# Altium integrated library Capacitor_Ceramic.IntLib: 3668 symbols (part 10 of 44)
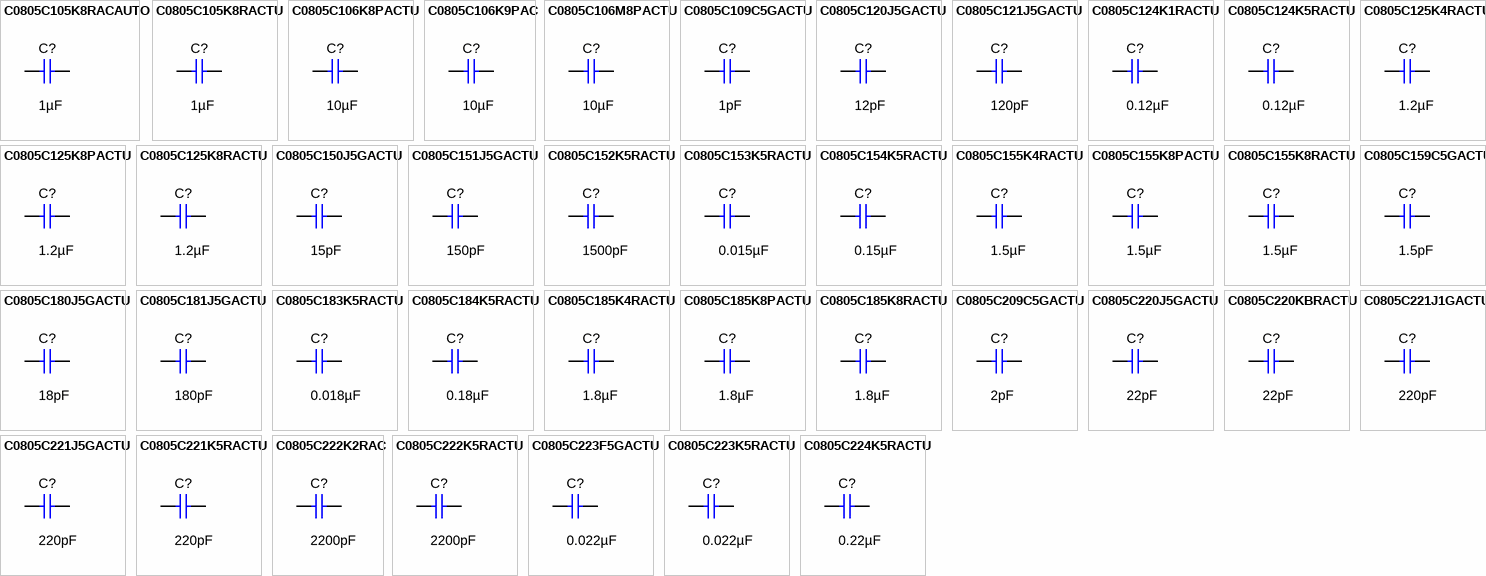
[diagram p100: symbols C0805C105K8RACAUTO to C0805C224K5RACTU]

## C0805C106K9PAC
designator C?  ValueDisplayed: 10µF  (hidden comment: C0805C106K9PAC)
CAP, CERM, 10 µF, 6.3 V,+/- 10%, X5R, 0805; Manufacturer: Kemet; Polarized: N; CompType: Capacitor; Value: 10uF; U/M: EA; Cap_F: 0.00001; Tolerance_%: 10; VDC_V: 6.3; Value2: 6.3V; TaMin_C: -55; TaMax_C: 85; Cap_Case: 0805; SizeArea_mm2: 2.5; SizeAreaWB_mm2: 6.75; SizeX_mm: 2; SizeY_mm: 1.25; SizeZ_mm: 1.45; AEC Category: Q200; Green_Lifecycle: Not Set; Green_REACh: Incomplete
signal-integrity model Cap
simulation model Cap
footprint 0805_HV
footprint 0805_HV1
footprint 0805
footprint 0805M
footprint 0805L
pins: 1, 2

## C0805C106M8PACTU
designator C?  ValueDisplayed: 10µF  (hidden comment: C0805C106M8PACTU)
CAP, CERM, 10 µF, 10 V,+/- 20%, X5R, 0805; Manufacturer: Kemet; Polarized: N; CompType: Capacitor; Value: 10uF; U/M: EA; Cap_F: 0.00001; Tolerance_%: 20; ESR_ohm: 0.003; Value1: 0.003 ohm; VDC_V: 10; Value2: 10V; IRMS_A: 11.43; TaMin_C: -55; TaMax_C: 85; Cap_Case: 0805; SizeArea_mm2: 2.5; SizeAreaWB_mm2: 6.75; SizeX_mm: 2; SizeY_mm: 1.25; SizeZ_mm: 1.45; AEC Category: Q200; Green_Lifecycle: Active; Green_REACh: Passed
signal-integrity model Cap
simulation model Cap
footprint 0805_HV
footprint 0805_HV1
footprint 0805
footprint 0805M
footprint 0805L
pins: 1, 2

## C0805C109C5GACTU
designator C?  ValueDisplayed: 1pF  (hidden comment: C0805C109C5GACTU)
CAP, CERM, 1 pF, 50 V,+/- 25%, C0G/NP0, 0805; Manufacturer: Kemet; Polarized: N; CompType: Capacitor; Value: 1pF; U/M: EA; Cap_F: 0.000000000001; Tolerance_%: 25; ESR_ohm: 0.84; Value1: 0.84 ohm; VDC_V: 50; Value2: 50V; IRMS_A: 0.023; TaMin_C: -55; TaMax_C: 125; Cap_Case: 0805; SizeArea_mm2: 2.5; SizeAreaWB_mm2: 6.75; SizeX_mm: 2; SizeY_mm: 1.25; SizeZ_mm: 1.45; AEC Category: Q200; Green_Lifecycle: Not Set; Green_REACh: Incomplete
signal-integrity model Cap
simulation model Cap
footprint 0805_HV
footprint 0805_HV1
footprint 0805
footprint 0805M
footprint 0805L
pins: 1, 2

## C0805C120J5GACTU
designator C?  ValueDisplayed: 12pF  (hidden comment: C0805C120J5GACTU)
CAP, CERM, 12 pF, 50 V,+/- 5%, C0G/NP0, 0805; Manufacturer: Kemet; Polarized: N; CompType: Capacitor; Value: 12pF; U/M: EA; Cap_F: 0.000000000012; Tolerance_%: 5; ESR_ohm: 0.252; Value1: 0.252 ohm; VDC_V: 50; Value2: 50V; IRMS_A: 0.265; TaMin_C: -55; TaMax_C: 125; Cap_Case: 0805; SizeArea_mm2: 2.5; SizeAreaWB_mm2: 6.75; SizeX_mm: 2; SizeY_mm: 1.25; SizeZ_mm: 1.45; AEC Category: Q200; Green_Lifecycle: Not Set; Green_REACh: Incomplete
signal-integrity model Cap
simulation model Cap
footprint 0805_HV
footprint 0805_HV1
footprint 0805
footprint 0805M
footprint 0805L
pins: 1, 2

## C0805C121J5GACTU
designator C?  ValueDisplayed: 120pF  (hidden comment: C0805C121J5GACTU)
CAP, CERM, 120 pF, 50 V,+/- 5%, C0G/NP0, 0805; Manufacturer: Kemet; Polarized: N; CompType: Capacitor; Value: 120pF; U/M: EA; Cap_F: 0.00000000012; Tolerance_%: 5; ESR_ohm: 0.066; Value1: 0.066 ohm; VDC_V: 50; Value2: 50V; IRMS_A: 0.615; TaMin_C: -55; TaMax_C: 125; Cap_Case: 0805; SizeArea_mm2: 2.5; SizeAreaWB_mm2: 6.75; SizeX_mm: 2; SizeY_mm: 1.25; SizeZ_mm: 1.45; AEC Category: Q200; Green_Lifecycle: Not Set; Green_REACh: Incomplete
signal-integrity model Cap
simulation model Cap
footprint 0805_HV
footprint 0805_HV1
footprint 0805
footprint 0805M
footprint 0805L
pins: 1, 2

## C0805C124K1RACTU
designator C?  ValueDisplayed: 0.12µF  (hidden comment: C0805C124K1RACTU)
CAP, CERM, 0.12 µF, 100 V,+/- 10%, X7R, 0805; Manufacturer: Kemet; Polarized: N; CompType: Capacitor; Value: 0.12uF; U/M: EA; Cap_F: 0.00000012; Tolerance_%: 10; ESR_ohm: 0.059; Value1: 0.059 ohm; VDC_V: 100; Value2: 100V; IRMS_A: 1.84; TaMin_C: -55; TaMax_C: 125; Cap_Case: 0805; SizeArea_mm2: 2.5; SizeAreaWB_mm2: 6.75; SizeX_mm: 2; SizeY_mm: 1.25; SizeZ_mm: 1.45; AEC Category: Q200; Green_Lifecycle: Not Set; Green_REACh: Incomplete
signal-integrity model Cap
simulation model Cap
footprint 0805_HV
footprint 0805_HV1
footprint 0805
footprint 0805M
footprint 0805L
pins: 1, 2

## C0805C124K5RACTU
designator C?  ValueDisplayed: 0.12µF  (hidden comment: C0805C124K5RACTU)
CAP, CERM, 0.12 µF, 50 V,+/- 10%, X7R, 0805; Manufacturer: Kemet; Polarized: N; CompType: Capacitor; Value: 0.12uF; U/M: EA; Cap_F: 0.00000012; Tolerance_%: 10; ESR_ohm: 0.059; Value1: 0.059 ohm; VDC_V: 50; Value2: 50V; IRMS_A: 1.84; TaMin_C: -55; TaMax_C: 125; Cap_Case: 0805; SizeArea_mm2: 2.5; SizeAreaWB_mm2: 6.75; SizeX_mm: 2; SizeY_mm: 1.25; SizeZ_mm: 1.45; AEC Category: Q200; Green_Lifecycle: Not Set; Green_REACh: Incomplete
signal-integrity model Cap
simulation model Cap
footprint 0805_HV
footprint 0805_HV1
footprint 0805
footprint 0805M
footprint 0805L
pins: 1, 2

## C0805C125K4RACTU
designator C?  ValueDisplayed: 1.2µF  (hidden comment: C0805C125K4RACTU)
CAP, CERM, 1.2 µF, 16 V,+/- 10%, X7R, 0805; Manufacturer: Kemet; Polarized: N; CompType: Capacitor; Value: 1.2uF; U/M: EA; Cap_F: 0.0000012; Tolerance_%: 10; ESR_ohm: 0.01; Value1: 0.01 ohm; VDC_V: 16; Value2: 16V; IRMS_A: 11.37; TaMin_C: -55; TaMax_C: 125; Cap_Case: 0805; SizeArea_mm2: 2.5; SizeAreaWB_mm2: 6.75; SizeX_mm: 2; SizeY_mm: 1.25; SizeZ_mm: 1.45; AEC Category: Q200; Green_Lifecycle: Not Set; Green_REACh: Incomplete
signal-integrity model Cap
simulation model Cap
footprint 0805_HV
footprint 0805_HV1
footprint 0805
footprint 0805M
footprint 0805L
pins: 1, 2

## C0805C125K8PACTU
designator C?  ValueDisplayed: 1.2µF  (hidden comment: C0805C125K8PACTU)
CAP, CERM, 1.2 µF, 10 V,+/- 10%, X5R, 0805; Manufacturer: Kemet; Polarized: N; CompType: Capacitor; Value: 1.2uF; U/M: EA; Cap_F: 0.0000012; Tolerance_%: 10; ESR_ohm: 0.009; Value1: 0.009 ohm; Value2: 10V; IRMS_A: 5.54; TaMin_C: -55; TaMax_C: 85; Cap_Case: 0805; SizeArea_mm2: 2.5; SizeAreaWB_mm2: 6.75; SizeX_mm: 2; SizeY_mm: 1.25; SizeZ_mm: 1.45; AEC Category: Q200; Green_Lifecycle: Not Set; Green_REACh: Incomplete
signal-integrity model Cap
simulation model Cap
footprint 0805_HV
footprint 0805_HV1
footprint 0805
footprint 0805M
footprint 0805L
pins: 1, 2

## C0805C125K8RACTU
designator C?  ValueDisplayed: 1.2µF  (hidden comment: C0805C125K8RACTU)
CAP, CERM, 1.2 µF, 10 V,+/- 10%, X7R, 0805; Manufacturer: Kemet; Polarized: N; CompType: Capacitor; Value: 1.2uF; U/M: EA; Cap_F: 0.0000012; Tolerance_%: 10; ESR_ohm: 0.01; Value1: 0.01 ohm; Value2: 10V; IRMS_A: 11.37; TaMin_C: -55; TaMax_C: 125; Cap_Case: 0805; SizeArea_mm2: 2.5; SizeAreaWB_mm2: 6.75; SizeX_mm: 2; SizeY_mm: 1.25; SizeZ_mm: 1.45; AEC Category: Q200; Green_Lifecycle: Not Set; Green_REACh: Incomplete
signal-integrity model Cap
simulation model Cap
footprint 0805_HV
footprint 0805_HV1
footprint 0805
footprint 0805M
footprint 0805L
pins: 1, 2

## C0805C150J5GACTU
designator C?  ValueDisplayed: 15pF  (hidden comment: C0805C150J5GACTU)
CAP, CERM, 15 pF, 50 V,+/- 5%, C0G/NP0, 0805; Manufacturer: Kemet; Polarized: N; CompType: Capacitor; Value: 15pF; U/M: EA; Cap_F: 0.000000000015; Tolerance_%: 5; ESR_ohm: 0.217; Value1: 0.217 ohm; VDC_V: 50; Value2: 50V; IRMS_A: 0.331; TaMin_C: -55; TaMax_C: 125; Cap_Case: 0805; SizeArea_mm2: 2.5; SizeAreaWB_mm2: 6.75; SizeX_mm: 2; SizeY_mm: 1.25; SizeZ_mm: 1.45; AEC Category: Q200; Green_Lifecycle: Not Set; Green_REACh: Incomplete
signal-integrity model Cap
simulation model Cap
footprint 0805_HV
footprint 0805_HV1
footprint 0805
footprint 0805M
footprint 0805L
pins: 1, 2

## C0805C151J5GACTU
designator C?  ValueDisplayed: 150pF  (hidden comment: C0805C151J5GACTU)
CAP, CERM, 150 pF, 50 V,+/- 5%, C0G/NP0, 0805; Manufacturer: Kemet; Polarized: N; CompType: Capacitor; Value: 150pF; U/M: EA; Cap_F: 0.00000000015; Tolerance_%: 5; ESR_ohm: 0.06; Value1: 0.06 ohm; VDC_V: 50; Value2: 50V; IRMS_A: 0.676; TaMin_C: -55; TaMax_C: 125; Cap_Case: 0805; SizeArea_mm2: 2.5; SizeAreaWB_mm2: 6.75; SizeX_mm: 2; SizeY_mm: 1.25; SizeZ_mm: 1.45; AEC Category: Q200; Green_Lifecycle: Active; Green_REACh: Passed
signal-integrity model Cap
simulation model Cap
footprint 0805_HV
footprint 0805_HV1
footprint 0805
footprint 0805M
footprint 0805L
pins: 1, 2

## C0805C152K5RACTU
designator C?  ValueDisplayed: 1500pF  (hidden comment: C0805C152K5RACTU)
CAP, CERM, 1500 pF, 50 V,+/- 10%, X7R, 0805; Manufacturer: Kemet; Polarized: N; CompType: Capacitor; Value: 1500pF; U/M: EA; Cap_F: 0.0000000015; Tolerance_%: 10; ESR_ohm: 0.475; Value1: 0.475 ohm; VDC_V: 50; Value2: 50V; IRMS_A: 0.188; TaMin_C: -55; TaMax_C: 125; Cap_Case: 0805; SizeArea_mm2: 2.5; SizeAreaWB_mm2: 6.75; SizeX_mm: 2; SizeY_mm: 1.25; SizeZ_mm: 1.45; AEC Category: Q200; Green_Lifecycle: Not Set; Green_REACh: Incomplete
signal-integrity model Cap
simulation model Cap
footprint 0805_HV
footprint 0805_HV1
footprint 0805
footprint 0805M
footprint 0805L
pins: 1, 2

## C0805C153K5RACTU
designator C?  ValueDisplayed: 0.015µF  (hidden comment: C0805C153K5RACTU)
CAP, CERM, 0.015 µF, 50 V,+/- 10%, X7R, 0805; Manufacturer: Kemet; Polarized: N; CompType: Capacitor; Value: 0.015uF; U/M: EA; Cap_F: 0.000000015; Tolerance_%: 10; ESR_ohm: 0.124; Value1: 0.124 ohm; VDC_V: 50; Value2: 50V; IRMS_A: 0.555; TaMin_C: -55; TaMax_C: 125; Cap_Case: 0805; SizeArea_mm2: 2.5; SizeAreaWB_mm2: 6.75; SizeX_mm: 2; SizeY_mm: 1.25; SizeZ_mm: 1.45; AEC Category: Q200; Green_Lifecycle: Not Set; Green_REACh: Incomplete
signal-integrity model Cap
simulation model Cap
footprint 0805_HV
footprint 0805_HV1
footprint 0805
footprint 0805M
footprint 0805L
pins: 1, 2

## C0805C154K5RACTU
designator C?  ValueDisplayed: 0.15µF  (hidden comment: C0805C154K5RACTU)
CAP, CERM, 0.15 µF, 50 V,+/- 10%, X7R, 0805; Manufacturer: Kemet; Polarized: N; CompType: Capacitor; Value: 0.15uF; U/M: EA; Cap_F: 0.00000015; Tolerance_%: 10; ESR_ohm: 0.054; Value1: 0.054 ohm; VDC_V: 50; Value2: 50V; IRMS_A: 2.09; TaMin_C: -55; TaMax_C: 125; Cap_Case: 0805; SizeArea_mm2: 2.5; SizeAreaWB_mm2: 6.75; SizeX_mm: 2; SizeY_mm: 1.25; SizeZ_mm: 1.45; AEC Category: Q200; Green_Lifecycle: Active; Green_REACh: Passed
signal-integrity model Cap
simulation model Cap
footprint 0805_HV
footprint 0805_HV1
footprint 0805
footprint 0805M
footprint 0805L
pins: 1, 2

## C0805C155K4RACTU
designator C?  ValueDisplayed: 1.5µF  (hidden comment: C0805C155K4RACTU)
CAP, CERM, 1.5 µF, 16 V,+/- 10%, X7R, 0805; Manufacturer: Kemet; Polarized: N; CompType: Capacitor; Value: 1.5uF; U/M: EA; Cap_F: 0.0000015; Tolerance_%: 10; ESR_ohm: 0.009; Value1: 0.009 ohm; VDC_V: 16; Value2: 16V; IRMS_A: 12.74; TaMin_C: -55; TaMax_C: 125; Cap_Case: 0805; SizeArea_mm2: 2.5; SizeAreaWB_mm2: 6.75; SizeX_mm: 2; SizeY_mm: 1.25; SizeZ_mm: 1.45; AEC Category: Q200; Green_Lifecycle: Not Set; Green_REACh: Incomplete
signal-integrity model Cap
simulation model Cap
footprint 0805_HV
footprint 0805_HV1
footprint 0805
footprint 0805M
footprint 0805L
pins: 1, 2

## C0805C155K8PACTU
designator C?  ValueDisplayed: 1.5µF  (hidden comment: C0805C155K8PACTU)
CAP, CERM, 1.5 µF, 10 V,+/- 10%, X5R, 0805; Manufacturer: Kemet; Polarized: N; CompType: Capacitor; Value: 1.5uF; U/M: EA; Cap_F: 0.0000015; Tolerance_%: 10; ESR_ohm: 0.009; Value1: 0.009 ohm; Value2: 10V; IRMS_A: 5.6; TaMin_C: -55; TaMax_C: 85; Cap_Case: 0805; SizeArea_mm2: 2.5; SizeAreaWB_mm2: 6.75; SizeX_mm: 2; SizeY_mm: 1.25; SizeZ_mm: 1.45; AEC Category: Q200; Green_Lifecycle: Not Set; Green_REACh: Incomplete
signal-integrity model Cap
simulation model Cap
footprint 0805_HV
footprint 0805_HV1
footprint 0805
footprint 0805M
footprint 0805L
pins: 1, 2

## C0805C155K8RACTU
designator C?  ValueDisplayed: 1.5µF  (hidden comment: C0805C155K8RACTU)
CAP, CERM, 1.5 µF, 10 V,+/- 10%, X7R, 0805; Manufacturer: Kemet; Polarized: N; CompType: Capacitor; Value: 1.5uF; U/M: EA; Cap_F: 0.0000015; Tolerance_%: 10; ESR_ohm: 0.009; Value1: 0.009 ohm; Value2: 10V; IRMS_A: 12.74; TaMin_C: -55; TaMax_C: 125; Cap_Case: 0805; SizeArea_mm2: 2.5; SizeAreaWB_mm2: 6.75; SizeX_mm: 2; SizeY_mm: 1.25; SizeZ_mm: 1.45; AEC Category: Q200; Green_Lifecycle: Not Set; Green_REACh: Incomplete
signal-integrity model Cap
simulation model Cap
footprint 0805_HV
footprint 0805_HV1
footprint 0805
footprint 0805M
footprint 0805L
pins: 1, 2

## C0805C159C5GACTU
designator C?  ValueDisplayed: 1.5pF  (hidden comment: C0805C159C5GACTU)
CAP, CERM, 1.5 pF, 50 V,+/- 17%, C0G/NP0, 0805; Manufacturer: Kemet; Polarized: N; CompType: Capacitor; Value: 1.5pF; U/M: EA; Cap_F: 0.0000000000015; Tolerance_%: 17; ESR_ohm: 0.765; Value1: 0.765 ohm; VDC_V: 50; Value2: 50V; IRMS_A: 0.032; TaMin_C: -55; TaMax_C: 125; Cap_Case: 0805; SizeArea_mm2: 2.5; SizeAreaWB_mm2: 6.75; SizeX_mm: 2; SizeY_mm: 1.25; SizeZ_mm: 1.45; AEC Category: Q200; Green_Lifecycle: Not Set; Green_REACh: Incomplete
signal-integrity model Cap
simulation model Cap
footprint 0805_HV
footprint 0805_HV1
footprint 0805
footprint 0805M
footprint 0805L
pins: 1, 2

## C0805C180J5GACTU
designator C?  ValueDisplayed: 18pF  (hidden comment: C0805C180J5GACTU)
CAP, CERM, 18 pF, 50 V,+/- 5%, C0G/NP0, 0805; Manufacturer: Kemet; Polarized: N; CompType: Capacitor; Value: 18pF; U/M: EA; Cap_F: 0.000000000018; Tolerance_%: 5; ESR_ohm: 0.193; Value1: 0.193 ohm; VDC_V: 50; Value2: 50V; IRMS_A: 0.38; TaMin_C: -55; TaMax_C: 125; Cap_Case: 0805; SizeArea_mm2: 2.5; SizeAreaWB_mm2: 6.75; SizeX_mm: 2; SizeY_mm: 1.25; SizeZ_mm: 1.45; AEC Category: Q200; Green_Lifecycle: Not Set; Green_REACh: Incomplete
signal-integrity model Cap
simulation model Cap
footprint 0805_HV
footprint 0805_HV1
footprint 0805
footprint 0805M
footprint 0805L
pins: 1, 2

## C0805C181J5GACTU
designator C?  ValueDisplayed: 180pF  (hidden comment: C0805C181J5GACTU)
CAP, CERM, 180 pF, 50 V,+/- 5%, C0G/NP0, 0805; Manufacturer: Kemet; Polarized: N; CompType: Capacitor; Value: 180pF; U/M: EA; Cap_F: 0.00000000018; Tolerance_%: 5; ESR_ohm: 0.053; Value1: 0.053 ohm; VDC_V: 50; Value2: 50V; IRMS_A: 0.782; TaMin_C: -55; TaMax_C: 125; Cap_Case: 0805; SizeArea_mm2: 2.5; SizeAreaWB_mm2: 6.75; SizeX_mm: 2; SizeY_mm: 1.25; SizeZ_mm: 1.45; AEC Category: Q200; Green_Lifecycle: Not Set; Green_REACh: Incomplete
signal-integrity model Cap
simulation model Cap
footprint 0805_HV
footprint 0805_HV1
footprint 0805
footprint 0805M
footprint 0805L
pins: 1, 2

## C0805C183K5RACTU
designator C?  ValueDisplayed: 0.018µF  (hidden comment: C0805C183K5RACTU)
CAP, CERM, 0.018 µF, 50 V,+/- 10%, X7R, 0805; Manufacturer: Kemet; Polarized: N; CompType: Capacitor; Value: 0.018uF; U/M: EA; Cap_F: 0.000000018; Tolerance_%: 10; ESR_ohm: 0.128; Value1: 0.128 ohm; VDC_V: 50; Value2: 50V; IRMS_A: 0.588; TaMin_C: -55; TaMax_C: 125; Cap_Case: 0805; SizeArea_mm2: 2.5; SizeAreaWB_mm2: 6.75; SizeX_mm: 2; SizeY_mm: 1.25; SizeZ_mm: 1.45; AEC Category: Q200; Green_Lifecycle: Not Set; Green_REACh: Incomplete
signal-integrity model Cap
simulation model Cap
footprint 0805_HV
footprint 0805_HV1
footprint 0805
footprint 0805M
footprint 0805L
pins: 1, 2

## C0805C184K5RACTU
designator C?  ValueDisplayed: 0.18µF  (hidden comment: C0805C184K5RACTU)
CAP, CERM, 0.18 µF, 50 V,+/- 10%, X7R, 0805; Manufacturer: Kemet; Polarized: N; CompType: Capacitor; Value: 0.18uF; U/M: EA; Cap_F: 0.00000018; Tolerance_%: 10; ESR_ohm: 0.051; Value1: 0.051 ohm; VDC_V: 50; Value2: 50V; IRMS_A: 2.33; TaMin_C: -55; TaMax_C: 125; Cap_Case: 0805; SizeArea_mm2: 2.5; SizeAreaWB_mm2: 6.75; SizeX_mm: 2; SizeY_mm: 1.25; SizeZ_mm: 1.45; AEC Category: Q200; Green_Lifecycle: Not Set; Green_REACh: Incomplete
signal-integrity model Cap
simulation model Cap
footprint 0805_HV
footprint 0805_HV1
footprint 0805
footprint 0805M
footprint 0805L
pins: 1, 2

## C0805C185K4RACTU
designator C?  ValueDisplayed: 1.8µF  (hidden comment: C0805C185K4RACTU)
CAP, CERM, 1.8 µF, 16 V,+/- 10%, X7R, 0805; Manufacturer: Kemet; Polarized: N; CompType: Capacitor; Value: 1.8uF; U/M: EA; Cap_F: 0.0000018; Tolerance_%: 10; ESR_ohm: 0.009; Value1: 0.009 ohm; VDC_V: 16; Value2: 16V; IRMS_A: 14.02; TaMin_C: -55; TaMax_C: 125; Cap_Case: 0805; SizeArea_mm2: 2.5; SizeAreaWB_mm2: 6.75; SizeX_mm: 2; SizeY_mm: 1.25; SizeZ_mm: 1.45; AEC Category: Q200; Green_Lifecycle: Not Set; Green_REACh: Incomplete
signal-integrity model Cap
simulation model Cap
footprint 0805_HV
footprint 0805_HV1
footprint 0805
footprint 0805M
footprint 0805L
pins: 1, 2

## C0805C185K8PACTU
designator C?  ValueDisplayed: 1.8µF  (hidden comment: C0805C185K8PACTU)
CAP, CERM, 1.8 µF, 10 V,+/- 10%, X5R, 0805; Manufacturer: Kemet; Polarized: N; CompType: Capacitor; Value: 1.8uF; U/M: EA; Cap_F: 0.0000018; Tolerance_%: 10; ESR_ohm: 0.005; Value1: 0.005 ohm; Value2: 10V; IRMS_A: 7.73; TaMin_C: -55; TaMax_C: 85; Cap_Case: 0805; SizeArea_mm2: 2.5; SizeAreaWB_mm2: 6.75; SizeX_mm: 2; SizeY_mm: 1.25; SizeZ_mm: 1.45; AEC Category: Q200; Green_Lifecycle: Not Set; Green_REACh: Incomplete
signal-integrity model Cap
simulation model Cap
footprint 0805_HV
footprint 0805_HV1
footprint 0805
footprint 0805M
footprint 0805L
pins: 1, 2

## C0805C185K8RACTU
designator C?  ValueDisplayed: 1.8µF  (hidden comment: C0805C185K8RACTU)
CAP, CERM, 1.8 µF, 10 V,+/- 10%, X7R, 0805; Manufacturer: Kemet; Polarized: N; CompType: Capacitor; Value: 1.8uF; U/M: EA; Cap_F: 0.0000018; Tolerance_%: 10; ESR_ohm: 0.009; Value1: 0.009 ohm; Value2: 10V; IRMS_A: 14.02; TaMin_C: -55; TaMax_C: 125; Cap_Case: 0805; SizeArea_mm2: 2.5; SizeAreaWB_mm2: 6.75; SizeX_mm: 2; SizeY_mm: 1.25; SizeZ_mm: 1.45; AEC Category: Q200; Green_Lifecycle: Not Set; Green_REACh: Incomplete
signal-integrity model Cap
simulation model Cap
footprint 0805_HV
footprint 0805_HV1
footprint 0805
footprint 0805M
footprint 0805L
pins: 1, 2

## C0805C209C5GACTU
designator C?  ValueDisplayed: 2pF  (hidden comment: C0805C209C5GACTU)
CAP, CERM, 2 pF, 50 V,+/- 13%, C0G/NP0, 0805; Manufacturer: Kemet; Polarized: N; CompType: Capacitor; Value: 2pF; U/M: EA; Cap_F: 0.000000000002; Tolerance_%: 13; ESR_ohm: 0.67; Value1: 0.67 ohm; VDC_V: 50; Value2: 50V; IRMS_A: 0.043; TaMin_C: -55; TaMax_C: 125; Cap_Case: 0805; SizeArea_mm2: 2.5; SizeAreaWB_mm2: 6.75; SizeX_mm: 2; SizeY_mm: 1.25; SizeZ_mm: 1.45; AEC Category: Q200; Green_Lifecycle: Not Set; Green_REACh: Incomplete
signal-integrity model Cap
simulation model Cap
footprint 0805_HV
footprint 0805_HV1
footprint 0805
footprint 0805M
footprint 0805L
pins: 1, 2

## C0805C220J5GACTU
designator C?  ValueDisplayed: 22pF  (hidden comment: C0805C220J5GACTU)
CAP, CERM, 22 pF, 50 V,+/- 5%, C0G/NP0, 0805; Manufacturer: Kemet; Polarized: N; CompType: Capacitor; Value: 22pF; U/M: EA; Cap_F: 0.000000000022; Tolerance_%: 5; ESR_ohm: 0.179; Value1: 0.179 ohm; VDC_V: 50; Value2: 50V; IRMS_A: 0.464; TaMin_C: -55; TaMax_C: 125; Cap_Case: 0805; SizeArea_mm2: 2.5; SizeAreaWB_mm2: 6.75; SizeX_mm: 2; SizeY_mm: 1.25; SizeZ_mm: 1.45; AEC Category: Q200; Green_Lifecycle: Not Set; Green_REACh: Incomplete
signal-integrity model Cap
simulation model Cap
footprint 0805_HV
footprint 0805_HV1
footprint 0805
footprint 0805M
footprint 0805L
pins: 1, 2

## C0805C220KBRACTU
designator C?  ValueDisplayed: 22pF  (hidden comment: C0805C220KBRACTU)
CAP, CERM, 22 pF, 630 V,+/- 10%, X7R, 0805; Manufacturer: Kemet; Polarized: N; CompType: Capacitor; Value: 22pF; U/M: EA; Cap_F: 0.000000000022; Tolerance_%: 10; VDC_V: 630; Value2: 630V; TaMin_C: -55; TaMax_C: 125; Cap_Case: 0805; SizeArea_mm2: 2.5; SizeAreaWB_mm2: 6.75; SizeX_mm: 2; SizeY_mm: 1.25; SizeZ_mm: 1.45; AEC Category: Q200; Green_Lifecycle: Active; Green_REACh: Passed
signal-integrity model Cap
simulation model Cap
footprint 0805_HV
footprint 0805_HV1
footprint 0805
footprint 0805M
footprint 0805L
pins: 1, 2

## C0805C221J1GACTU
designator C?  ValueDisplayed: 220pF  (hidden comment: C0805C221J1GACTU)
CAP, CERM, 220 pF, 100 V,+/- 5%, C0G/NP0, 0805; Manufacturer: Kemet; Polarized: N; CompType: Capacitor; Value: 220pF; U/M: EA; Cap_F: 0.00000000022; Tolerance_%: 5; ESR_ohm: 0.046; Value1: 0.046 ohm; VDC_V: 100; Value2: 100V; IRMS_A: 0.888; TaMin_C: -55; TaMax_C: 125; Cap_Case: 0805; SizeArea_mm2: 2.5; SizeAreaWB_mm2: 6.75; SizeX_mm: 2; SizeY_mm: 1.25; SizeZ_mm: 1.45; AEC Category: Q200; Green_Lifecycle: Not Set; Green_REACh: Incomplete
signal-integrity model Cap
simulation model Cap
footprint 0805_HV
footprint 0805_HV1
footprint 0805
footprint 0805M
footprint 0805L
pins: 1, 2

## C0805C221J5GACTU
designator C?  ValueDisplayed: 220pF  (hidden comment: C0805C221J5GACTU)
CAP, CERM, 220 pF, 50 V,+/- 5%, C0G/NP0, 0805; Manufacturer: Kemet; Polarized: N; CompType: Capacitor; Value: 220pF; U/M: EA; Cap_F: 0.00000000022; Tolerance_%: 5; ESR_ohm: 0.046; Value1: 0.046 ohm; VDC_V: 50; Value2: 50V; IRMS_A: 0.888; TaMin_C: -55; TaMax_C: 125; Cap_Case: 0805; SizeArea_mm2: 2.5; SizeAreaWB_mm2: 6.75; SizeX_mm: 2; SizeY_mm: 1.25; SizeZ_mm: 1.45; AEC Category: Q200; Green_Lifecycle: Not Set; Green_REACh: Incomplete
signal-integrity model Cap
simulation model Cap
footprint 0805_HV
footprint 0805_HV1
footprint 0805
footprint 0805M
footprint 0805L
pins: 1, 2

## C0805C221K5RACTU
designator C?  ValueDisplayed: 220pF  (hidden comment: C0805C221K5RACTU)
CAP, CERM, 220 pF, 50 V,+/- 10%, X7R, 0805; Manufacturer: Kemet; Polarized: N; CompType: Capacitor; Value: 220pF; U/M: EA; Cap_F: 0.00000000022; Tolerance_%: 10; ESR_ohm: 1.414; Value1: 1.414 ohm; VDC_V: 50; Value2: 50V; IRMS_A: 0.111; TaMin_C: -55; TaMax_C: 125; Cap_Case: 0805; SizeArea_mm2: 2.5; SizeAreaWB_mm2: 6.75; SizeX_mm: 2; SizeY_mm: 1.25; SizeZ_mm: 1.45; AEC Category: Q200; Green_Lifecycle: Active; Green_REACh: Passed
signal-integrity model Cap
simulation model Cap
footprint 0805_HV
footprint 0805_HV1
footprint 0805
footprint 0805M
footprint 0805L
pins: 1, 2

## C0805C222K2RAC
designator C?  ValueDisplayed: 2200pF  (hidden comment: C0805C222K2RAC)
CAP, CERM, 2200 pF, 200 V,+/- 10%, X7R, 0805; Manufacturer: Kemet; Polarized: N; CompType: Capacitor; Value: 2200pF; U/M: EA; Cap_F: 0.0000000022; Tolerance_%: 10; VDC_V: 200; Value2: 200V; TaMin_C: -55; TaMax_C: 125; Cap_Case: 0805; SizeArea_mm2: 2.5; SizeAreaWB_mm2: 6.75; SizeX_mm: 2; SizeY_mm: 1.25; SizeZ_mm: 1.45; AEC Category: Q200
signal-integrity model Cap
simulation model Cap
footprint 0805_HV
footprint 0805_HV1
footprint 0805
footprint 0805M
footprint 0805L
pins: 1, 2

## C0805C222K5RACTU
designator C?  ValueDisplayed: 2200pF  (hidden comment: C0805C222K5RACTU)
CAP, CERM, 2200 pF, 50 V,+/- 10%, X7R, 0805; Manufacturer: Kemet; Polarized: N; CompType: Capacitor; Value: 2200pF; U/M: EA; Cap_F: 0.0000000022; Tolerance_%: 10; ESR_ohm: 0.4; Value1: 0.4 ohm; VDC_V: 50; Value2: 50V; IRMS_A: 0.251; TaMin_C: -55; TaMax_C: 125; Cap_Case: 0805; SizeArea_mm2: 2.5; SizeAreaWB_mm2: 6.75; SizeX_mm: 2; SizeY_mm: 1.25; SizeZ_mm: 1.45; AEC Category: Q200; Green_Lifecycle: Active; Green_REACh: Passed
signal-integrity model Cap
simulation model Cap
footprint 0805_HV
footprint 0805_HV1
footprint 0805
footprint 0805M
footprint 0805L
pins: 1, 2

## C0805C223F5GACTU
designator C?  ValueDisplayed: 0.022µF  (hidden comment: C0805C223F5GACTU)
CAP, CERM, 0.022 µF, 50 V,+/- 1%, C0G/NP0, 0805; Manufacturer: Kemet; Polarized: N; CompType: Capacitor; Value: 0.022uF; U/M: EA; Cap_F: 0.000000022; Tolerance_%: 1; VDC_V: 50; Value2: 50V; TaMin_C: -55; TaMax_C: 125; Cap_Case: 0805; SizeArea_mm2: 2.5; SizeAreaWB_mm2: 6.75; SizeX_mm: 2; SizeY_mm: 1.25; SizeZ_mm: 1.45; AEC Category: Q200; Green_Lifecycle: Not Set; Green_REACh: Incomplete
signal-integrity model Cap
simulation model Cap
footprint 0805_HV
footprint 0805_HV1
footprint 0805
footprint 0805M
footprint 0805L
pins: 1, 2

## C0805C223K5RACTU
designator C?  ValueDisplayed: 0.022µF  (hidden comment: C0805C223K5RACTU)
CAP, CERM, 0.022 µF, 50 V,+/- 10%, X7R, 0805; Manufacturer: Kemet; Polarized: N; CompType: Capacitor; Value: 0.022uF; U/M: EA; Cap_F: 0.000000022; Tolerance_%: 10; ESR_ohm: 0.125; Value1: 0.125 ohm; VDC_V: 50; Value2: 50V; IRMS_A: 0.645; TaMin_C: -55; TaMax_C: 125; Cap_Case: 0805; SizeArea_mm2: 2.5; SizeAreaWB_mm2: 6.75; SizeX_mm: 2; SizeY_mm: 1.25; SizeZ_mm: 1.45; AEC Category: Q200; Green_Lifecycle: Active; Green_REACh: Passed
signal-integrity model Cap
simulation model Cap
footprint 0805_HV
footprint 0805_HV1
footprint 0805
footprint 0805M
footprint 0805L
pins: 1, 2

## C0805C224K5RACTU
designator C?  ValueDisplayed: 0.22µF  (hidden comment: C0805C224K5RACTU)
CAP, CERM, 0.22 µF, 50 V,+/- 10%, X7R, 0805; Manufacturer: Kemet; Polarized: N; CompType: Capacitor; Value: 0.22uF; U/M: EA; Cap_F: 0.00000022; Tolerance_%: 10; ESR_ohm: 0.046; Value1: 0.046 ohm; VDC_V: 50; Value2: 50V; IRMS_A: 2.65; TaMin_C: -55; TaMax_C: 125; Cap_Case: 0805; SizeArea_mm2: 2.5; SizeAreaWB_mm2: 6.75; SizeX_mm: 2; SizeY_mm: 1.25; SizeZ_mm: 1.45; AEC Category: Q200; Green_Lifecycle: Active; Green_REACh: Passed
signal-integrity model Cap
simulation model Cap
footprint 0805_HV
footprint 0805_HV1
footprint 0805
footprint 0805M
footprint 0805L
pins: 1, 2

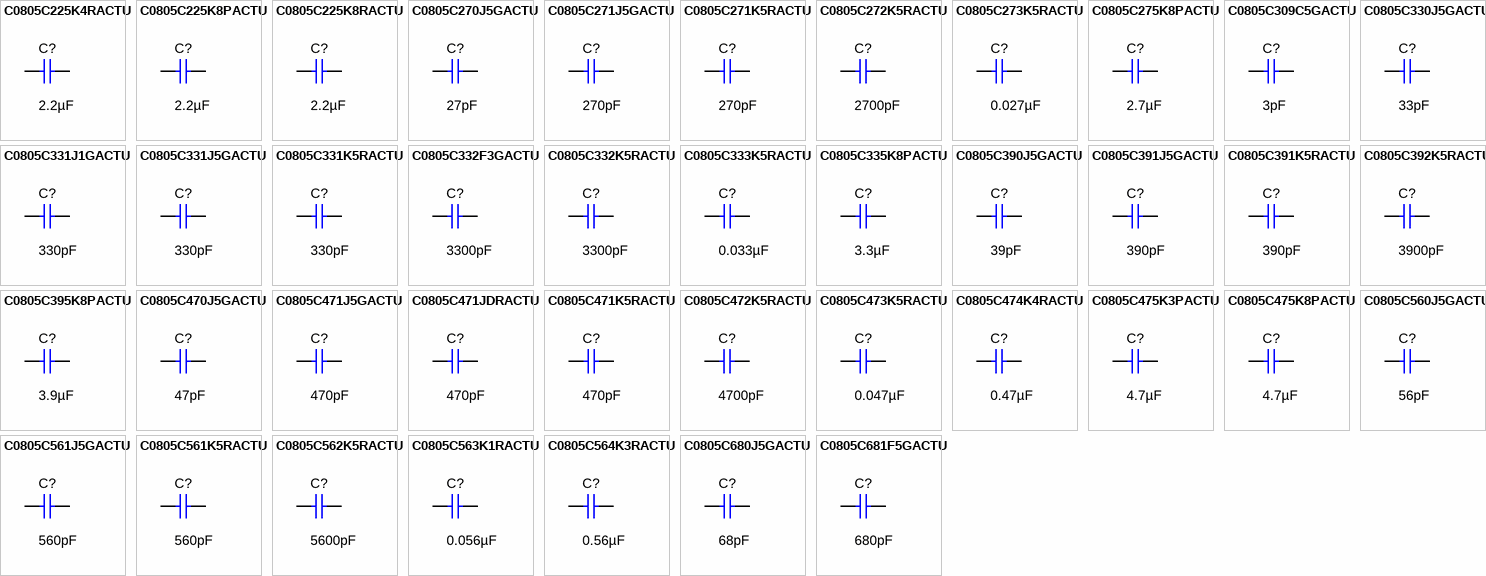
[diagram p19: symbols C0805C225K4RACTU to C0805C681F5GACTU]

## C0805C225K4RACTU
designator C?  ValueDisplayed: 2.2µF  (hidden comment: C0805C225K4RACTU)
CAP, CERM, 2.2 µF, 16 V,+/- 10%, X7R, 0805; Manufacturer: Kemet; Polarized: N; CompType: Capacitor; Value: 2.2uF; U/M: EA; Cap_F: 0.0000022; Tolerance_%: 10; ESR_ohm: 0.008; Value1: 0.008 ohm; VDC_V: 16; Value2: 16V; IRMS_A: 15.55; TaMin_C: -55; TaMax_C: 125; Cap_Case: 0805; SizeArea_mm2: 2.5; SizeAreaWB_mm2: 6.75; SizeX_mm: 2; SizeY_mm: 1.25; SizeZ_mm: 1.45; AEC Category: Q200; Green_Lifecycle: Active; Green_REACh: Passed
signal-integrity model Cap
simulation model Cap
footprint 0805_HV
footprint 0805_HV1
footprint 0805
footprint 0805M
footprint 0805L
pins: 1, 2

## C0805C225K8PACTU
designator C?  ValueDisplayed: 2.2µF  (hidden comment: C0805C225K8PACTU)
CAP, CERM, 2.2 µF, 10 V,+/- 10%, X5R, 0805; Manufacturer: Kemet; Polarized: N; CompType: Capacitor; Value: 2.2uF; U/M: EA; Cap_F: 0.0000022; Tolerance_%: 10; ESR_ohm: 0.006; Value1: 0.006 ohm; Value2: 10V; IRMS_A: 7.32; TaMin_C: -55; TaMax_C: 85; Cap_Case: 0805; SizeArea_mm2: 2.5; SizeAreaWB_mm2: 6.75; SizeX_mm: 2; SizeY_mm: 1.25; SizeZ_mm: 1.45; AEC Category: Q200; Green_Lifecycle: Not Set; Green_REACh: Incomplete
signal-integrity model Cap
simulation model Cap
footprint 0805_HV
footprint 0805_HV1
footprint 0805
footprint 0805M
footprint 0805L
pins: 1, 2

## C0805C225K8RACTU
designator C?  ValueDisplayed: 2.2µF  (hidden comment: C0805C225K8RACTU)
CAP, CERM, 2.2 µF, 10 V,+/- 10%, X7R, 0805; Manufacturer: Kemet; Polarized: N; CompType: Capacitor; Value: 2.2uF; U/M: EA; Cap_F: 0.0000022; Tolerance_%: 10; ESR_ohm: 0.008; Value1: 0.008 ohm; Value2: 10V; IRMS_A: 15.55; TaMin_C: -55; TaMax_C: 125; Cap_Case: 0805; SizeArea_mm2: 2.5; SizeAreaWB_mm2: 6.75; SizeX_mm: 2; SizeY_mm: 1.25; SizeZ_mm: 1.45; AEC Category: Q200; Green_Lifecycle: Active; Green_REACh: Passed
signal-integrity model Cap
simulation model Cap
footprint 0805_HV
footprint 0805_HV1
footprint 0805
footprint 0805M
footprint 0805L
pins: 1, 2

## C0805C270J5GACTU
designator C?  ValueDisplayed: 27pF  (hidden comment: C0805C270J5GACTU)
CAP, CERM, 27 pF, 50 V,+/- 5%, C0G/NP0, 0805; Manufacturer: Kemet; Polarized: N; CompType: Capacitor; Value: 27pF; U/M: EA; Cap_F: 0.000000000027; Tolerance_%: 5; ESR_ohm: 0.161; Value1: 0.161 ohm; VDC_V: 50; Value2: 50V; IRMS_A: 0.524; TaMin_C: -55; TaMax_C: 125; Cap_Case: 0805; SizeArea_mm2: 2.5; SizeAreaWB_mm2: 6.75; SizeX_mm: 2; SizeY_mm: 1.25; SizeZ_mm: 1.45; AEC Category: Q200; Green_Lifecycle: Not Set; Green_REACh: Incomplete
signal-integrity model Cap
simulation model Cap
footprint 0805_HV
footprint 0805_HV1
footprint 0805
footprint 0805M
footprint 0805L
pins: 1, 2

## C0805C271J5GACTU
designator C?  ValueDisplayed: 270pF  (hidden comment: C0805C271J5GACTU)
CAP, CERM, 270 pF, 50 V,+/- 5%, C0G/NP0, 0805; Manufacturer: Kemet; Polarized: N; CompType: Capacitor; Value: 270pF; U/M: EA; Cap_F: 0.00000000027; Tolerance_%: 5; ESR_ohm: 0.042; Value1: 0.042 ohm; VDC_V: 50; Value2: 50V; IRMS_A: 0.954; TaMin_C: -55; TaMax_C: 125; Cap_Case: 0805; SizeArea_mm2: 2.5; SizeAreaWB_mm2: 6.75; SizeX_mm: 2; SizeY_mm: 1.25; SizeZ_mm: 1.45; AEC Category: Q200; Green_Lifecycle: Active; Green_REACh: Passed
signal-integrity model Cap
simulation model Cap
footprint 0805_HV
footprint 0805_HV1
footprint 0805
footprint 0805M
footprint 0805L
pins: 1, 2

## C0805C271K5RACTU
designator C?  ValueDisplayed: 270pF  (hidden comment: C0805C271K5RACTU)
CAP, CERM, 270 pF, 50 V,+/- 10%, X7R, 0805; Manufacturer: Kemet; Polarized: N; CompType: Capacitor; Value: 270pF; U/M: EA; Cap_F: 0.00000000027; Tolerance_%: 10; ESR_ohm: 1.14; Value1: 1.14 ohm; VDC_V: 50; Value2: 50V; IRMS_A: 0.139; TaMin_C: -55; TaMax_C: 125; Cap_Case: 0805; SizeArea_mm2: 2.5; SizeAreaWB_mm2: 6.75; SizeX_mm: 2; SizeY_mm: 1.25; SizeZ_mm: 1.45; AEC Category: Q200; Green_Lifecycle: Not Set; Green_REACh: Incomplete
signal-integrity model Cap
simulation model Cap
footprint 0805_HV
footprint 0805_HV1
footprint 0805
footprint 0805M
footprint 0805L
pins: 1, 2

## C0805C272K5RACTU
designator C?  ValueDisplayed: 2700pF  (hidden comment: C0805C272K5RACTU)
CAP, CERM, 2700 pF, 50 V,+/- 10%, X7R, 0805; Manufacturer: Kemet; Polarized: N; CompType: Capacitor; Value: 2700pF; U/M: EA; Cap_F: 0.0000000027; Tolerance_%: 10; ESR_ohm: 0.364; Value1: 0.364 ohm; VDC_V: 50; Value2: 50V; IRMS_A: 0.283; TaMin_C: -55; TaMax_C: 125; Cap_Case: 0805; SizeArea_mm2: 2.5; SizeAreaWB_mm2: 6.75; SizeX_mm: 2; SizeY_mm: 1.25; SizeZ_mm: 1.45; AEC Category: Q200; Green_Lifecycle: Active; Green_REACh: Passed
signal-integrity model Cap
simulation model Cap
footprint 0805_HV
footprint 0805_HV1
footprint 0805
footprint 0805M
footprint 0805L
pins: 1, 2

## C0805C273K5RACTU
designator C?  ValueDisplayed: 0.027µF  (hidden comment: C0805C273K5RACTU)
CAP, CERM, 0.027 µF, 50 V,+/- 10%, X7R, 0805; Manufacturer: Kemet; Polarized: N; CompType: Capacitor; Value: 0.027uF; U/M: EA; Cap_F: 0.000000027; Tolerance_%: 10; ESR_ohm: 0.115; Value1: 0.115 ohm; VDC_V: 50; Value2: 50V; IRMS_A: 0.728; TaMin_C: -55; TaMax_C: 125; Cap_Case: 0805; SizeArea_mm2: 2.5; SizeAreaWB_mm2: 6.75; SizeX_mm: 2; SizeY_mm: 1.25; SizeZ_mm: 1.45; AEC Category: Q200; Green_Lifecycle: Not Set; Green_REACh: Incomplete
signal-integrity model Cap
simulation model Cap
footprint 0805_HV
footprint 0805_HV1
footprint 0805
footprint 0805M
footprint 0805L
pins: 1, 2

## C0805C275K8PACTU
designator C?  ValueDisplayed: 2.7µF  (hidden comment: C0805C275K8PACTU)
CAP, CERM, 2.7 µF, 10 V,+/- 10%, X5R, 0805; Manufacturer: Kemet; Polarized: N; CompType: Capacitor; Value: 2.7uF; U/M: EA; Cap_F: 0.0000027; Tolerance_%: 10; ESR_ohm: 0.006; Value1: 0.006 ohm; Value2: 10V; IRMS_A: 7.37; TaMin_C: -55; TaMax_C: 85; Cap_Case: 0805; SizeArea_mm2: 2.5; SizeAreaWB_mm2: 6.75; SizeX_mm: 2; SizeY_mm: 1.25; SizeZ_mm: 1.45; AEC Category: Q200; Green_Lifecycle: Not Set; Green_REACh: Incomplete
signal-integrity model Cap
simulation model Cap
footprint 0805_HV
footprint 0805_HV1
footprint 0805
footprint 0805M
footprint 0805L
pins: 1, 2

## C0805C309C5GACTU
designator C?  ValueDisplayed: 3pF  (hidden comment: C0805C309C5GACTU)
CAP, CERM, 3 pF, 50 V,+/- 8%, C0G/NP0, 0805; Manufacturer: Kemet; Polarized: N; CompType: Capacitor; Value: 3pF; U/M: EA; Cap_F: 0.000000000003; Tolerance_%: 8; ESR_ohm: 0.541; Value1: 0.541 ohm; VDC_V: 50; Value2: 50V; IRMS_A: 0.063; TaMin_C: -55; TaMax_C: 125; Cap_Case: 0805; SizeArea_mm2: 2.5; SizeAreaWB_mm2: 6.75; SizeX_mm: 2; SizeY_mm: 1.25; SizeZ_mm: 1.45; AEC Category: Q200; Green_Lifecycle: Not Set; Green_REACh: Incomplete
signal-integrity model Cap
simulation model Cap
footprint 0805_HV
footprint 0805_HV1
footprint 0805
footprint 0805M
footprint 0805L
pins: 1, 2

## C0805C330J5GACTU
designator C?  ValueDisplayed: 33pF  (hidden comment: C0805C330J5GACTU)
CAP, CERM, 33 pF, 50 V,+/- 5%, C0G/NP0, 0805; Manufacturer: Kemet; Polarized: N; CompType: Capacitor; Value: 33pF; U/M: EA; Cap_F: 0.000000000033; Tolerance_%: 5; ESR_ohm: 0.0143; Value1: 0.0143 ohm; VDC_V: 50; Value2: 50V; IRMS_A: 0.656; TaMin_C: -55; TaMax_C: 125; Cap_Case: 0805; SizeArea_mm2: 2.5; SizeAreaWB_mm2: 6.75; SizeX_mm: 2; SizeY_mm: 1.25; SizeZ_mm: 1.45; AEC Category: Q200; Green_Lifecycle: Active; Green_REACh: Passed
signal-integrity model Cap
simulation model Cap
footprint 0805_HV
footprint 0805_HV1
footprint 0805
footprint 0805M
footprint 0805L
pins: 1, 2

## C0805C331J1GACTU
designator C?  ValueDisplayed: 330pF  (hidden comment: C0805C331J1GACTU)
CAP, CERM, 330 pF, 100 V,+/- 5%, C0G/NP0, 0805; Manufacturer: Kemet; Polarized: N; CompType: Capacitor; Value: 330pF; U/M: EA; Cap_F: 0.00000000033; Tolerance_%: 5; ESR_ohm: 0.038; Value1: 0.038 ohm; VDC_V: 100; Value2: 100V; IRMS_A: 1.04; TaMin_C: -55; TaMax_C: 125; Cap_Case: 0805; SizeArea_mm2: 2.5; SizeAreaWB_mm2: 6.75; SizeX_mm: 2; SizeY_mm: 1.25; SizeZ_mm: 1.45; AEC Category: Q200; Green_Lifecycle: Not Set; Green_REACh: Incomplete
signal-integrity model Cap
simulation model Cap
footprint 0805_HV
footprint 0805_HV1
footprint 0805
footprint 0805M
footprint 0805L
pins: 1, 2

## C0805C331J5GACTU
designator C?  ValueDisplayed: 330pF  (hidden comment: C0805C331J5GACTU)
CAP, CERM, 330 pF, 50 V,+/- 5%, C0G/NP0, 0805; Manufacturer: Kemet; Polarized: N; CompType: Capacitor; Value: 330pF; U/M: EA; Cap_F: 0.00000000033; Tolerance_%: 5; ESR_ohm: 0.038; Value1: 0.038 ohm; VDC_V: 50; Value2: 50V; IRMS_A: 1.04; TaMin_C: -55; TaMax_C: 125; Cap_Case: 0805; SizeArea_mm2: 2.5; SizeAreaWB_mm2: 6.75; SizeX_mm: 2; SizeY_mm: 1.25; SizeZ_mm: 1.45; AEC Category: Q200; Green_Lifecycle: Not Set; Green_REACh: Incomplete
signal-integrity model Cap
simulation model Cap
footprint 0805_HV
footprint 0805_HV1
footprint 0805
footprint 0805M
footprint 0805L
pins: 1, 2

## C0805C331K5RACTU
designator C?  ValueDisplayed: 330pF  (hidden comment: C0805C331K5RACTU)
CAP, CERM, 330 pF, 50 V,+/- 10%, X7R, 0805; Manufacturer: Kemet; Polarized: N; CompType: Capacitor; Value: 330pF; U/M: EA; Cap_F: 0.00000000033; Tolerance_%: 10; ESR_ohm: 0.935; Value1: 0.935 ohm; VDC_V: 50; Value2: 50V; IRMS_A: 0.167; TaMin_C: -55; TaMax_C: 125; Cap_Case: 0805; SizeArea_mm2: 2.5; SizeAreaWB_mm2: 6.75; SizeX_mm: 2; SizeY_mm: 1.25; SizeZ_mm: 1.45; AEC Category: Q200; Green_Lifecycle: Not Set; Green_REACh: Incomplete
signal-integrity model Cap
simulation model Cap
footprint 0805_HV
footprint 0805_HV1
footprint 0805
footprint 0805M
footprint 0805L
pins: 1, 2

## C0805C332F3GACTU
designator C?  ValueDisplayed: 3300pF  (hidden comment: C0805C332F3GACTU)
CAP, CERM, 3300 pF, 25 V,+/- 1%, C0G/NP0, 0805; Manufacturer: Kemet; Polarized: N; CompType: Capacitor; Value: 3300pF; U/M: EA; Cap_F: 0.0000000033; Tolerance_%: 1; VDC_V: 25; Value2: 25V; TaMin_C: -55; TaMax_C: 125; Cap_Case: 0805; SizeArea_mm2: 2.5; SizeAreaWB_mm2: 6.75; SizeX_mm: 2; SizeY_mm: 1.25; SizeZ_mm: 1.45; AEC Category: Q200; Green_Lifecycle: Not Set; Green_REACh: Incomplete
signal-integrity model Cap
simulation model Cap
footprint 0805_HV
footprint 0805_HV1
footprint 0805
footprint 0805M
footprint 0805L
pins: 1, 2

## C0805C332K5RACTU
designator C?  ValueDisplayed: 3300pF  (hidden comment: C0805C332K5RACTU)
CAP, CERM, 3300 pF, 50 V,+/- 10%, X7R, 0805; Manufacturer: Kemet; Polarized: N; CompType: Capacitor; Value: 3300pF; U/M: EA; Cap_F: 0.0000000033; Tolerance_%: 10; ESR_ohm: 0.332; Value1: 0.332 ohm; VDC_V: 50; Value2: 50V; IRMS_A: 0.319; TaMin_C: -55; TaMax_C: 125; Cap_Case: 0805; SizeArea_mm2: 2.5; SizeAreaWB_mm2: 6.75; SizeX_mm: 2; SizeY_mm: 1.25; SizeZ_mm: 1.45; AEC Category: Q200; Green_Lifecycle: Not Set; Green_REACh: Incomplete
signal-integrity model Cap
simulation model Cap
footprint 0805_HV
footprint 0805_HV1
footprint 0805
footprint 0805M
footprint 0805L
pins: 1, 2

## C0805C333K5RACTU
designator C?  ValueDisplayed: 0.033µF  (hidden comment: C0805C333K5RACTU)
CAP, CERM, 0.033 µF, 50 V,+/- 10%, X7R, 0805; Manufacturer: Kemet; Polarized: N; CompType: Capacitor; Value: 0.033uF; U/M: EA; Cap_F: 0.000000033; Tolerance_%: 10; ESR_ohm: 0.104; Value1: 0.104 ohm; VDC_V: 50; Value2: 50V; IRMS_A: 0.831; TaMin_C: -55; TaMax_C: 125; Cap_Case: 0805; SizeArea_mm2: 2.5; SizeAreaWB_mm2: 6.75; SizeX_mm: 2; SizeY_mm: 1.25; SizeZ_mm: 1.45; AEC Category: Q200; Green_Lifecycle: Active; Green_REACh: Passed
signal-integrity model Cap
simulation model Cap
footprint 0805_HV
footprint 0805_HV1
footprint 0805
footprint 0805M
footprint 0805L
pins: 1, 2

## C0805C335K8PACTU
designator C?  ValueDisplayed: 3.3µF  (hidden comment: C0805C335K8PACTU)
CAP, CERM, 3.3 µF, 10 V,+/- 10%, X5R, 0805; Manufacturer: Kemet; Polarized: N; CompType: Capacitor; Value: 3.3uF; U/M: EA; Cap_F: 0.0000033; Tolerance_%: 10; ESR_ohm: 0.005; Value1: 0.005 ohm; Value2: 10V; IRMS_A: 8.13; TaMin_C: -55; TaMax_C: 85; Cap_Case: 0805; SizeArea_mm2: 2.5; SizeAreaWB_mm2: 6.75; SizeX_mm: 2; SizeY_mm: 1.25; SizeZ_mm: 1.45; AEC Category: Q200; Green_Lifecycle: Not Set; Green_REACh: Incomplete
signal-integrity model Cap
simulation model Cap
footprint 0805_HV
footprint 0805_HV1
footprint 0805
footprint 0805M
footprint 0805L
pins: 1, 2

## C0805C390J5GACTU
designator C?  ValueDisplayed: 39pF  (hidden comment: C0805C390J5GACTU)
CAP, CERM, 39 pF, 50 V,+/- 5%, C0G/NP0, 0805; Manufacturer: Kemet; Polarized: N; CompType: Capacitor; Value: 39pF; U/M: EA; Cap_F: 0.000000000039; Tolerance_%: 5; ESR_ohm: 0.13; Value1: 0.13 ohm; VDC_V: 50; Value2: 50V; IRMS_A: 0.653; TaMin_C: -55; TaMax_C: 125; Cap_Case: 0805; SizeArea_mm2: 2.5; SizeAreaWB_mm2: 6.75; SizeX_mm: 2; SizeY_mm: 1.25; SizeZ_mm: 1.45; AEC Category: Q200; Green_Lifecycle: Not Set; Green_REACh: Incomplete
signal-integrity model Cap
simulation model Cap
footprint 0805_HV
footprint 0805_HV1
footprint 0805
footprint 0805M
footprint 0805L
pins: 1, 2

## C0805C391J5GACTU
designator C?  ValueDisplayed: 390pF  (hidden comment: C0805C391J5GACTU)
CAP, CERM, 390 pF, 50 V,+/- 5%, C0G/NP0, 0805; Manufacturer: Kemet; Polarized: N; CompType: Capacitor; Value: 390pF; U/M: EA; Cap_F: 0.00000000039; Tolerance_%: 5; ESR_ohm: 0.033; Value1: 0.033 ohm; VDC_V: 50; Value2: 50V; IRMS_A: 1.07; TaMin_C: -55; TaMax_C: 125; Cap_Case: 0805; SizeArea_mm2: 2.5; SizeAreaWB_mm2: 6.75; SizeX_mm: 2; SizeY_mm: 1.25; SizeZ_mm: 1.45; AEC Category: Q200; Green_Lifecycle: Not Set; Green_REACh: Incomplete
signal-integrity model Cap
simulation model Cap
footprint 0805_HV
footprint 0805_HV1
footprint 0805
footprint 0805M
footprint 0805L
pins: 1, 2

## C0805C391K5RACTU
designator C?  ValueDisplayed: 390pF  (hidden comment: C0805C391K5RACTU)
CAP, CERM, 390 pF, 50 V,+/- 10%, X7R, 0805; Manufacturer: Kemet; Polarized: N; CompType: Capacitor; Value: 390pF; U/M: EA; Cap_F: 0.00000000039; Tolerance_%: 10; ESR_ohm: 0.818; Value1: 0.818 ohm; VDC_V: 50; Value2: 50V; IRMS_A: 0.193; TaMin_C: -55; TaMax_C: 125; Cap_Case: 0805; SizeArea_mm2: 2.5; SizeAreaWB_mm2: 6.75; SizeX_mm: 2; SizeY_mm: 1.25; SizeZ_mm: 1.45; AEC Category: Q200; Green_Lifecycle: Not Set; Green_REACh: Incomplete
signal-integrity model Cap
simulation model Cap
footprint 0805_HV
footprint 0805_HV1
footprint 0805
footprint 0805M
footprint 0805L
pins: 1, 2

## C0805C392K5RACTU
designator C?  ValueDisplayed: 3900pF  (hidden comment: C0805C392K5RACTU)
CAP, CERM, 3900 pF, 50 V,+/- 10%, X7R, 0805; Manufacturer: Kemet; Polarized: N; CompType: Capacitor; Value: 3900pF; U/M: EA; Cap_F: 0.0000000039; Tolerance_%: 10; ESR_ohm: 0.31; Value1: 0.31 ohm; VDC_V: 50; Value2: 50V; IRMS_A: 0.35; TaMin_C: -55; TaMax_C: 125; Cap_Case: 0805; SizeArea_mm2: 2.5; SizeAreaWB_mm2: 6.75; SizeX_mm: 2; SizeY_mm: 1.25; SizeZ_mm: 1.45; AEC Category: Q200; Green_Lifecycle: Not Set; Green_REACh: Incomplete
signal-integrity model Cap
simulation model Cap
footprint 0805_HV
footprint 0805_HV1
footprint 0805
footprint 0805M
footprint 0805L
pins: 1, 2

## C0805C395K8PACTU
designator C?  ValueDisplayed: 3.9µF  (hidden comment: C0805C395K8PACTU)
CAP, CERM, 3.9 µF, 10 V,+/- 10%, X5R, 0805; Manufacturer: Kemet; Polarized: N; CompType: Capacitor; Value: 3.9uF; U/M: EA; Cap_F: 0.0000039; Tolerance_%: 10; ESR_ohm: 0.004; Value1: 0.004 ohm; Value2: 10V; IRMS_A: 8.5; TaMin_C: -55; TaMax_C: 85; Cap_Case: 0805; SizeArea_mm2: 2.5; SizeAreaWB_mm2: 6.75; SizeX_mm: 2; SizeY_mm: 1.25; SizeZ_mm: 1.45; AEC Category: Q200; Green_Lifecycle: Not Set; Green_REACh: Incomplete
signal-integrity model Cap
simulation model Cap
footprint 0805_HV
footprint 0805_HV1
footprint 0805
footprint 0805M
footprint 0805L
pins: 1, 2

## C0805C470J5GACTU
designator C?  ValueDisplayed: 47pF  (hidden comment: C0805C470J5GACTU)
CAP, CERM, 47 pF, 50 V,+/- 5%, C0G/NP0, 0805; Manufacturer: Kemet; Polarized: N; CompType: Capacitor; Value: 47pF; U/M: EA; Cap_F: 0.000000000047; Tolerance_%: 5; ESR_ohm: 0.115; Value1: 0.115 ohm; VDC_V: 50; Value2: 50V; IRMS_A: 0.505; TaMin_C: -55; TaMax_C: 125; Cap_Case: 0805; SizeArea_mm2: 2.5; SizeAreaWB_mm2: 6.75; SizeX_mm: 2; SizeY_mm: 1.25; SizeZ_mm: 1.45; AEC Category: Q200; Green_Lifecycle: Active; Green_REACh: Passed
signal-integrity model Cap
simulation model Cap
footprint 0805_HV
footprint 0805_HV1
footprint 0805
footprint 0805M
footprint 0805L
pins: 1, 2

## C0805C471J5GACTU
designator C?  ValueDisplayed: 470pF  (hidden comment: C0805C471J5GACTU)
CAP, CERM, 470 pF, 50 V,+/- 5%, C0G/NP0, 0805; Manufacturer: Kemet; Polarized: N; CompType: Capacitor; Value: 470pF; U/M: EA; Cap_F: 0.00000000047; Tolerance_%: 5; ESR_ohm: 0.03; Value1: 0.03 ohm; VDC_V: 50; Value2: 50V; IRMS_A: 1.29; TaMin_C: -55; TaMax_C: 125; Cap_Case: 0805; SizeArea_mm2: 2.5; SizeAreaWB_mm2: 6.75; SizeX_mm: 2; SizeY_mm: 1.25; SizeZ_mm: 1.45; AEC Category: Q200; Green_Lifecycle: Not Set; Green_REACh: Incomplete
signal-integrity model Cap
simulation model Cap
footprint 0805_HV
footprint 0805_HV1
footprint 0805
footprint 0805M
footprint 0805L
pins: 1, 2

## C0805C471JDRACTU
designator C?  ValueDisplayed: 470pF  (hidden comment: C0805C471JDRACTU)
CAP, CERM, 470 pF, 1000 V,+/- 5%, X7R, 0805; Manufacturer: Kemet; Polarized: N; CompType: Capacitor; Value: 470pF; U/M: EA; Cap_F: 0.00000000047; Tolerance_%: 5; VDC_V: 1000; Value2: 1000V; TaMin_C: -55; TaMax_C: 125; Cap_Case: 0805; SizeArea_mm2: 2.5; SizeAreaWB_mm2: 6.75; SizeX_mm: 2; SizeY_mm: 1.25; SizeZ_mm: 1.45; AEC Category: Q200
signal-integrity model Cap
simulation model Cap
footprint 0805_HV
footprint 0805_HV1
footprint 0805
footprint 0805M
footprint 0805L
pins: 1, 2

## C0805C471K5RACTU
designator C?  ValueDisplayed: 470pF  (hidden comment: C0805C471K5RACTU)
CAP, CERM, 470 pF, 50 V,+/- 10%, X7R, 0805; Manufacturer: Kemet; Polarized: N; CompType: Capacitor; Value: 470pF; U/M: EA; Cap_F: 0.00000000047; Tolerance_%: 10; ESR_ohm: 0.688; Value1: 0.688 ohm; VDC_V: 50; Value2: 50V; IRMS_A: 0.213; TaMin_C: -55; TaMax_C: 125; Cap_Case: 0805; SizeArea_mm2: 2.5; SizeAreaWB_mm2: 6.75; SizeX_mm: 2; SizeY_mm: 1.25; SizeZ_mm: 1.45; AEC Category: Q200; Green_Lifecycle: Active; Green_REACh: Passed
signal-integrity model Cap
simulation model Cap
footprint 0805_HV
footprint 0805_HV1
footprint 0805
footprint 0805M
footprint 0805L
pins: 1, 2

## C0805C472K5RACTU
designator C?  ValueDisplayed: 4700pF  (hidden comment: C0805C472K5RACTU)
CAP, CERM, 4700 pF, 50 V,+/- 10%, X7R, 0805; Manufacturer: Kemet; Polarized: N; CompType: Capacitor; Value: 4700pF; U/M: EA; Cap_F: 0.0000000047; Tolerance_%: 10; ESR_ohm: 0.279; Value1: 0.279 ohm; VDC_V: 50; Value2: 50V; IRMS_A: 0.321; TaMin_C: -55; TaMax_C: 125; Cap_Case: 0805; SizeArea_mm2: 2.5; SizeAreaWB_mm2: 6.75; SizeX_mm: 2; SizeY_mm: 1.25; SizeZ_mm: 1.45; AEC Category: Q200; Green_Lifecycle: Active; Green_REACh: Passed
signal-integrity model Cap
simulation model Cap
footprint 0805_HV
footprint 0805_HV1
footprint 0805
footprint 0805M
footprint 0805L
pins: 1, 2

## C0805C473K5RACTU
designator C?  ValueDisplayed: 0.047µF  (hidden comment: C0805C473K5RACTU)
CAP, CERM, 0.047 µF, 50 V,+/- 10%, X7R, 0805; Manufacturer: Kemet; Polarized: N; CompType: Capacitor; Value: 0.047uF; U/M: EA; Cap_F: 0.000000047; Tolerance_%: 10; ESR_ohm: 0.088; Value1: 0.088 ohm; VDC_V: 50; Value2: 50V; IRMS_A: 1.04; TaMin_C: -55; TaMax_C: 125; Cap_Case: 0805; SizeArea_mm2: 2.5; SizeAreaWB_mm2: 6.75; SizeX_mm: 2; SizeY_mm: 1.25; SizeZ_mm: 1.45; AEC Category: Q200; Green_Lifecycle: Active; Green_REACh: Passed
signal-integrity model Cap
simulation model Cap
footprint 0805_HV
footprint 0805_HV1
footprint 0805
footprint 0805M
footprint 0805L
pins: 1, 2

## C0805C474K4RACTU
designator C?  ValueDisplayed: 0.47µF  (hidden comment: C0805C474K4RACTU)
CAP, CERM, 0.47 µF, 16 V,+/- 10%, X7R, 0805; Manufacturer: Kemet; Polarized: N; CompType: Capacitor; Value: 0.47uF; U/M: EA; Cap_F: 0.00000047; Tolerance_%: 10; VDC_V: 16; Value2: 16V; TaMin_C: -55; TaMax_C: 125; Cap_Case: 0805; SizeArea_mm2: 2.5; SizeAreaWB_mm2: 6.75; SizeX_mm: 2; SizeY_mm: 1.25; SizeZ_mm: 1.45; AEC Category: Q200; Green_Lifecycle: Active; Green_REACh: Passed
signal-integrity model Cap
simulation model Cap
footprint 0805_HV
footprint 0805_HV1
footprint 0805
footprint 0805M
footprint 0805L
pins: 1, 2

## C0805C475K3PACTU
designator C?  ValueDisplayed: 4.7µF  (hidden comment: C0805C475K3PACTU)
CAP, CERM, 4.7 µF, 25 V,+/- 10%, X5R, 0805; Manufacturer: Kemet; Polarized: N; CompType: Capacitor; Value: 4.7uF; U/M: EA; Cap_F: 0.0000047; Tolerance_%: 10; VDC_V: 25; Value2: 25V; TaMin_C: -55; TaMax_C: 85; Cap_Case: 0805; SizeArea_mm2: 2.5; SizeAreaWB_mm2: 6.75; SizeX_mm: 2; SizeY_mm: 1.25; SizeZ_mm: 1.45; AEC Category: Q200; Green_Lifecycle: Active; Green_REACh: Passed
signal-integrity model Cap
simulation model Cap
footprint 0805_HV
footprint 0805_HV1
footprint 0805
footprint 0805M
footprint 0805L
pins: 1, 2

## C0805C475K8PACTU
designator C?  ValueDisplayed: 4.7µF  (hidden comment: C0805C475K8PACTU)
CAP, CERM, 4.7 µF, 10 V,+/- 10%, X5R, 0805; Manufacturer: Kemet; Polarized: N; CompType: Capacitor; Value: 4.7uF; U/M: EA; Cap_F: 0.0000047; Tolerance_%: 10; ESR_ohm: 0.004; Value1: 0.004 ohm; Value2: 10V; IRMS_A: 9.89; TaMin_C: -55; TaMax_C: 85; Cap_Case: 0805; SizeArea_mm2: 2.5; SizeAreaWB_mm2: 6.75; SizeX_mm: 2; SizeY_mm: 1.25; SizeZ_mm: 1.45; AEC Category: Q200; Green_Lifecycle: Active; Green_REACh: Passed
signal-integrity model Cap
simulation model Cap
footprint 0805_HV
footprint 0805_HV1
footprint 0805
footprint 0805M
footprint 0805L
pins: 1, 2

## C0805C560J5GACTU
designator C?  ValueDisplayed: 56pF  (hidden comment: C0805C560J5GACTU)
CAP, CERM, 56 pF, 50 V,+/- 5%, C0G/NP0, 0805; Manufacturer: Kemet; Polarized: N; CompType: Capacitor; Value: 56pF; U/M: EA; Cap_F: 0.000000000056; Tolerance_%: 5; ESR_ohm: 0.103; Value1: 0.103 ohm; VDC_V: 50; Value2: 50V; IRMS_A: 0.541; TaMin_C: -55; TaMax_C: 125; Cap_Case: 0805; SizeArea_mm2: 2.5; SizeAreaWB_mm2: 6.75; SizeX_mm: 2; SizeY_mm: 1.25; SizeZ_mm: 1.45; AEC Category: Q200; Green_Lifecycle: Active; Green_REACh: Passed
signal-integrity model Cap
simulation model Cap
footprint 0805_HV
footprint 0805_HV1
footprint 0805
footprint 0805M
footprint 0805L
pins: 1, 2

## C0805C561J5GACTU
designator C?  ValueDisplayed: 560pF  (hidden comment: C0805C561J5GACTU)
CAP, CERM, 560 pF, 50 V,+/- 5%, C0G/NP0, 0805; Manufacturer: Kemet; Polarized: N; CompType: Capacitor; Value: 560pF; U/M: EA; Cap_F: 0.00000000056; Tolerance_%: 5; ESR_ohm: 0.029; Value1: 0.029 ohm; VDC_V: 50; Value2: 50V; IRMS_A: 1.24; TaMin_C: -55; TaMax_C: 125; Cap_Case: 0805; SizeArea_mm2: 2.5; SizeAreaWB_mm2: 6.75; SizeX_mm: 2; SizeY_mm: 1.25; SizeZ_mm: 1.45; AEC Category: Q200; Green_Lifecycle: Not Set; Green_REACh: Incomplete
signal-integrity model Cap
simulation model Cap
footprint 0805_HV
footprint 0805_HV1
footprint 0805
footprint 0805M
footprint 0805L
pins: 1, 2

## C0805C561K5RACTU
designator C?  ValueDisplayed: 560pF  (hidden comment: C0805C561K5RACTU)
CAP, CERM, 560 pF, 50 V,+/- 10%, X7R, 0805; Manufacturer: Kemet; Polarized: N; CompType: Capacitor; Value: 560pF; U/M: EA; Cap_F: 0.00000000056; Tolerance_%: 10; ESR_ohm: 0.577; Value1: 0.577 ohm; VDC_V: 50; Value2: 50V; IRMS_A: 0.234; TaMin_C: -55; TaMax_C: 125; Cap_Case: 0805; SizeArea_mm2: 2.5; SizeAreaWB_mm2: 6.75; SizeX_mm: 2; SizeY_mm: 1.25; SizeZ_mm: 1.45; AEC Category: Q200; Green_Lifecycle: Not Set; Green_REACh: Incomplete
signal-integrity model Cap
simulation model Cap
footprint 0805_HV
footprint 0805_HV1
footprint 0805
footprint 0805M
footprint 0805L
pins: 1, 2

## C0805C562K5RACTU
designator C?  ValueDisplayed: 5600pF  (hidden comment: C0805C562K5RACTU)
CAP, CERM, 5600 pF, 50 V,+/- 10%, X7R, 0805; Manufacturer: Kemet; Polarized: N; CompType: Capacitor; Value: 5600pF; U/M: EA; Cap_F: 0.0000000056; Tolerance_%: 10; ESR_ohm: 0.199; Value1: 0.199 ohm; VDC_V: 50; Value2: 50V; IRMS_A: 0.297; TaMin_C: -55; TaMax_C: 125; Cap_Case: 0805; SizeArea_mm2: 2.5; SizeAreaWB_mm2: 6.75; SizeX_mm: 2; SizeY_mm: 1.25; SizeZ_mm: 1.45; AEC Category: Q200; Green_Lifecycle: Not Set; Green_REACh: Incomplete
signal-integrity model Cap
simulation model Cap
footprint 0805_HV
footprint 0805_HV1
footprint 0805
footprint 0805M
footprint 0805L
pins: 1, 2

## C0805C563K1RACTU
designator C?  ValueDisplayed: 0.056µF  (hidden comment: C0805C563K1RACTU)
CAP, CERM, 0.056 µF, 100 V,+/- 10%, X7R, 0805; Manufacturer: Kemet; Polarized: N; CompType: Capacitor; Value: 0.056uF; U/M: EA; Cap_F: 0.000000056; Tolerance_%: 10; ESR_ohm: 0.085; Value1: 0.085 ohm; VDC_V: 100; Value2: 100V; IRMS_A: 1.13; TaMin_C: -55; TaMax_C: 125; Cap_Case: 0805; SizeArea_mm2: 2.5; SizeAreaWB_mm2: 6.75; SizeX_mm: 2; SizeY_mm: 1.25; SizeZ_mm: 1.45; AEC Category: Q200; Green_Lifecycle: Not Set; Green_REACh: Incomplete
signal-integrity model Cap
simulation model Cap
footprint 0805_HV
footprint 0805_HV1
footprint 0805
footprint 0805M
footprint 0805L
pins: 1, 2

## C0805C564K3RACTU
designator C?  ValueDisplayed: 0.56µF  (hidden comment: C0805C564K3RACTU)
CAP, CERM, 0.56 µF, 25 V,+/- 10%, X7R, 0805; Manufacturer: Kemet; Polarized: N; CompType: Capacitor; Value: 0.56uF; U/M: EA; Cap_F: 0.00000056; Tolerance_%: 10; ESR_ohm: 0.021; Value1: 0.021 ohm; VDC_V: 25; Value2: 25V; IRMS_A: 5.57; TaMin_C: -55; TaMax_C: 125; Cap_Case: 0805; SizeArea_mm2: 2.5; SizeAreaWB_mm2: 6.75; SizeX_mm: 2; SizeY_mm: 1.25; SizeZ_mm: 1.45; AEC Category: Q200; Green_Lifecycle: Active; Green_REACh: Passed
signal-integrity model Cap
simulation model Cap
footprint 0805_HV
footprint 0805_HV1
footprint 0805
footprint 0805M
footprint 0805L
pins: 1, 2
